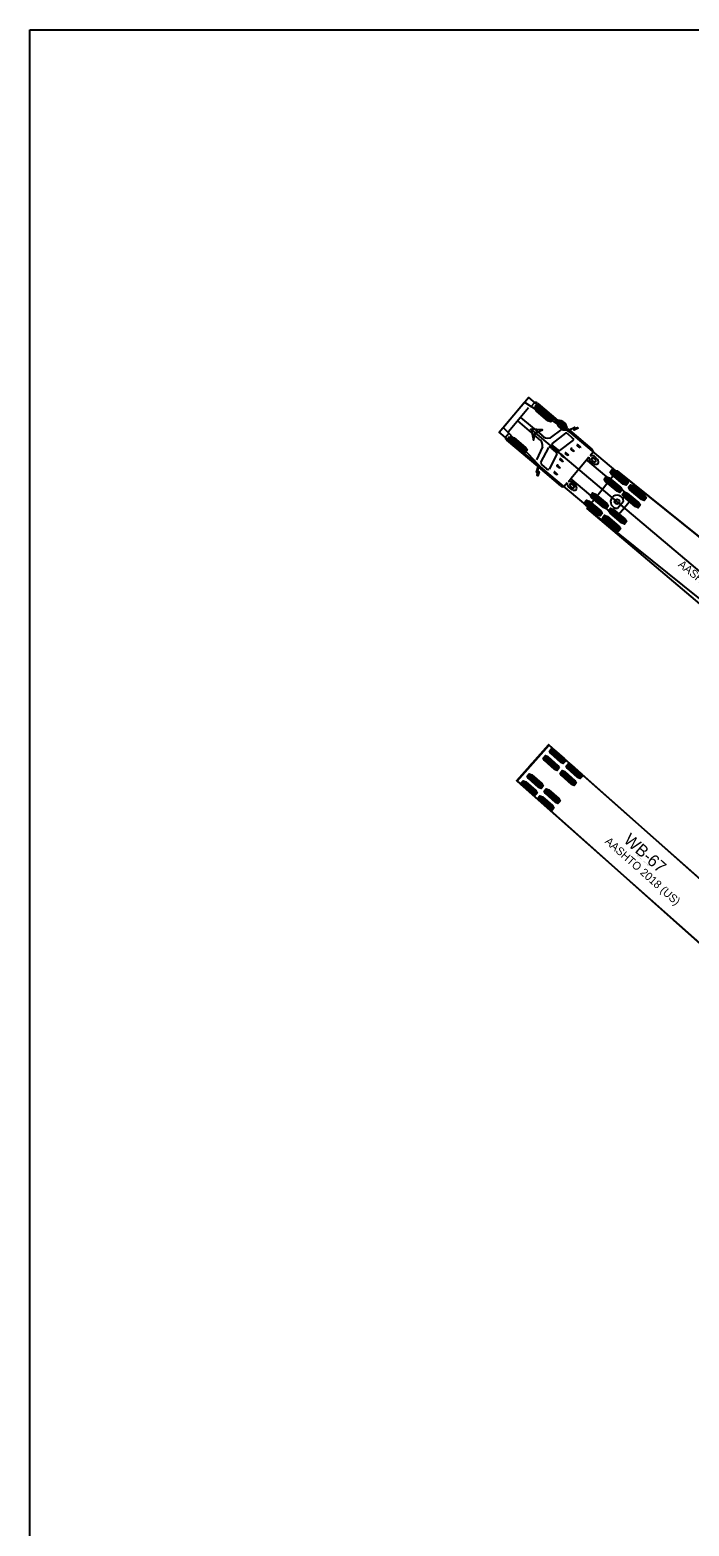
# Model space of a CAD drawing. Extents: x 973688 to 979179, y 703586 to 707602.
# Drawn here: x 976318.3 to 976435, y 705537.8 to 705802.7 of the extents above; entities that cross this region are included whole.
import ezdxf

# ---------------------------------------------------------------- set-up
doc = ezdxf.new("R2010")
doc.units = 0
for name, color, linetype in [('EB Right', 7, 'Continuous'), ('NO PLOT', 7, 'Continuous'), ('SB Right', 7, 'Continuous')]:
    doc.layers.add(name, color=color, linetype=linetype)

msp = doc.modelspace()

# ---------------------------------------------------------------- linework, layer by layer
at = {"layer": 'EB Right'}
for p, q in [((976404.6, 705669.7), (976410.24, 705676.06)), ((976413.09, 705673.23), (976410.62, 705675.42)), ((976407.01, 705672.53), (976407.19, 705672.73)), ((976407.37, 705672.93), (976407.42, 705672.88)), ((976407.54, 705673.13), (976407.72, 705673.33)), ((976411.69, 705671.65), (976409.22, 705673.84)), ((976411.84, 705671.82), (976409.37, 705674.01)), ((976411.99, 705671.99), (976409.52, 705674.19)), ((976412.78, 705672.89), (976410.31, 705675.08)), ((976412.93, 705673.06), (976410.47, 705675.25)), ((976416.08, 705670.57), (976413.61, 705672.76)), ((976408.84, 705668.45), (976406.38, 705670.64)), ((976409, 705668.62), (976406.53, 705670.81)), ((976409.15, 705668.79), (976406.68, 705670.98)), ((976414.68, 705669), (976412.21, 705671.19)), ((976414.83, 705669.17), (976412.36, 705671.36)), ((976414.98, 705669.34), (976412.51, 705671.53)), ((976415.77, 705670.23), (976413.31, 705672.42)), ((976415.93, 705670.4), (976413.46, 705672.59)), ((976407.75, 705667.21), (976405.28, 705669.4)), ((976407.9, 705667.39), (976405.43, 705669.58)), ((976408.05, 705667.56), (976405.58, 705669.75)), ((976411.84, 705665.79), (976409.37, 705667.98)), ((976411.99, 705665.96), (976409.52, 705668.16)), ((976412.14, 705666.14), (976409.67, 705668.33)), ((976410.74, 705664.56), (976408.27, 705666.75)), ((976410.89, 705664.73), (976408.42, 705666.92)), ((976411.04, 705664.9), (976408.58, 705667.09))]:
    msp.add_line(p, q, dxfattribs=at)
for points in [[(976442.37, 705636.04), (976434.45, 705643.15), (976418.56, 705657.31), (976404.49, 705669.8), (976410.14, 705676.15), (976410.14, 705676.15)], [(976404.56, 705669.77), (976404.55, 705669.75), (976404.6, 705669.7), (976408.84, 705665.94), (976444.14, 705634.62), (976446.96, 705637.8), (976449.78, 705640.98), (976414.48, 705672.3), (976410.24, 705676.06), (976410.19, 705676.11), (976410.17, 705676.09)], [(976410.16, 705676.07), (976410.16, 705676.07), (976407.74, 705673.35), (976407.72, 705673.33), (976407.67, 705673.37), (976407.67, 705673.37), (976407.49, 705673.17)], [(976410.14, 705676.15), (976440.9, 705648.86)], [(976407.14, 705672.78), (976406.96, 705672.58), (976406.96, 705672.58), (976407.01, 705672.53), (976406.99, 705672.5), (976404.58, 705669.79), (976404.58, 705669.79)], [(976407.54, 705673.12), (976407.19, 705672.73)]]:
    msp.add_lwpolyline(points, dxfattribs=at)
for points in [[(976413.12, 705673.27), (976412.74, 705672.84), (976412.28, 705673.02), (976410.51, 705674.6), (976410.28, 705675.03), (976410.66, 705675.46), (976411.12, 705675.28), (976412.89, 705673.71)], [(976412.03, 705672.04), (976411.65, 705671.61), (976411.19, 705671.79), (976409.41, 705673.36), (976409.18, 705673.8), (976409.56, 705674.23), (976410.02, 705674.05), (976411.8, 705672.47)], [(976416.12, 705670.62), (976415.74, 705670.19), (976415.28, 705670.37), (976413.5, 705671.94), (976413.27, 705672.38), (976413.65, 705672.81), (976414.11, 705672.63), (976415.88, 705671.05)], [(976409.19, 705668.83), (976408.81, 705668.41), (976408.35, 705668.58), (976406.57, 705670.16), (976406.34, 705670.6), (976406.72, 705671.02), (976407.18, 705670.85), (976408.95, 705669.27)], [(976415.02, 705669.38), (976414.64, 705668.95), (976414.18, 705669.13), (976412.4, 705670.71), (976412.17, 705671.14), (976412.55, 705671.57), (976413.01, 705671.4), (976414.79, 705669.82)], [(976408.09, 705667.6), (976407.71, 705667.17), (976407.25, 705667.35), (976405.47, 705668.93), (976405.24, 705669.36), (976405.62, 705669.79), (976406.08, 705669.61), (976407.86, 705668.03)], [(976412.18, 705666.18), (976411.8, 705665.75), (976411.34, 705665.93), (976409.56, 705667.51), (976409.33, 705667.94), (976409.71, 705668.37), (976410.17, 705668.19), (976411.95, 705666.61)], [(976411.08, 705664.94), (976410.7, 705664.52), (976410.24, 705664.69), (976408.47, 705666.27), (976408.23, 705666.71), (976408.61, 705667.13), (976409.07, 705666.96), (976410.85, 705665.38)]]:
    msp.add_lwpolyline(points, close=True, dxfattribs=at)
for centre in [(976410.14, 705676.11), (976404.54, 705669.8)]:
    msp.add_circle(centre, 0.0266, dxfattribs=at)
for centre, radius, start, end in [((976410.14, 705676.11), 0.0363, 337.4928, 298.6541), ((976407.17, 705672.76), 0.0354, 142.7069, 314.8923), ((976407.17, 705672.76), 0.0352, 319.3896, 138.3901), ((976407.51, 705673.15), 0.0352, 138.4406, 317.441), ((976407.51, 705673.15), 0.0353, 321.7515, 140.1012), ((976403.05, 705671.11), 2.02, 318.4153, 319.0991)]:
    msp.add_arc(centre, radius, start, end, dxfattribs=at)
at = {"layer": 'NO PLOT'}
msp.add_lwpolyline([(976318.34, 705802.71), (976998.34, 705802.71), (976998.34, 705362.71), (976318.34, 705362.71)], close=True, dxfattribs=at)
at = {"layer": 'SB Right'}
for p, q in [((976407.91, 705736.29), (976407.65, 705735.97)), ((976408.18, 705736.06), (976407.91, 705736.29)), ((976406.6, 705735.82), (976403.01, 705731.57)), ((976405.17, 705734.12), (976408.91, 705730.97)), ((976411.58, 705733.02), (976407.06, 705736.02)), ((976407.65, 705735.97), (976407.92, 705735.74)), ((976407.77, 705735.71), (976410.57, 705733.35)), ((976407.92, 705735.74), (976408.18, 705736.06)), ((976407.92, 705735.89), (976410.72, 705733.52)), ((976408.07, 705736.06), (976410.87, 705733.7)), ((976410.08, 705723.88), (976403.08, 705731.3)), ((976404.63, 705733.48), (976408.37, 705730.33)), ((976549.41, 705611.94), (976407.04, 705732)), ((976410.46, 705730.51), (976412.54, 705732)), ((976413.13, 705731.3), (976410.74, 705729.47)), ((976415.56, 705730.37), (976413.22, 705731.93)), ((976414.38, 705730.46), (976413.52, 705731.19)), ((976413.84, 705731.82), (976413.76, 705731.89)), ((976414.82, 705732.18), (976414.84, 705732.2)), ((976414.84, 705732.2), (976414.87, 705732.21)), ((976402.96, 705730.41), (976403.23, 705730.73)), ((976403.23, 705730.18), (976402.96, 705730.41)), ((976403.2, 705730.3), (976406.01, 705727.93)), ((976403.23, 705730.73), (976403.5, 705730.5)), ((976403.5, 705730.5), (976403.23, 705730.18)), ((976403.35, 705730.47), (976406.15, 705728.11)), ((976403.5, 705730.65), (976406.3, 705728.28)), ((976409.08, 705728.88), (976407.97, 705726.58)), ((976408.75, 705726.11), (976410.15, 705728.77)), ((976410.57, 705728.68), (976411.43, 705727.96)), ((976410.9, 705729.08), (976411.76, 705728.35)), ((976412.15, 705728.24), (976414.54, 705730.07)), ((976414.62, 705728.06), (976414.18, 705728.38)), ((976414.29, 705728.51), (976414.68, 705728.13)), ((976415.7, 705728.74), (976415.26, 705729.07)), ((976415.37, 705729.19), (976415.76, 705728.81)), ((976415.76, 705728.81), (976415.7, 705728.74)), ((976409.8, 705725.02), (976408.93, 705725.75)), ((976411.61, 705727.59), (976410.21, 705724.93)), ((976412.67, 705726.26), (976412.23, 705726.59)), ((976412.34, 705726.72), (976412.73, 705726.33)), ((976412.89, 705727), (976412.45, 705727.33)), ((976412.56, 705727.46), (976412.95, 705727.07)), ((976412.73, 705726.33), (976412.67, 705726.26)), ((976412.95, 705727.07), (976412.89, 705727)), ((976413.58, 705727.34), (976413.14, 705727.67)), ((976413.25, 705727.8), (976413.64, 705727.41)), ((976413.64, 705727.41), (976413.58, 705727.34)), ((976416.84, 705726.56), (976414.05, 705723.25)), ((976414.68, 705728.13), (976414.62, 705728.06)), ((976408.17, 705724.29), (976408.15, 705724.27)), ((976408.15, 705724.27), (976408.15, 705724.25)), ((976408.36, 705725.33), (976408.28, 705725.39)), ((976411.65, 705723.94), (976411.21, 705724.26)), ((976411.32, 705724.39), (976411.71, 705724.01)), ((976411.71, 705724.01), (976411.65, 705723.94)), ((976412.14, 705725.12), (976411.68, 705725.46)), ((976411.79, 705725.59), (976412.2, 705725.19)), ((976412.2, 705725.19), (976412.14, 705725.12)), ((976420.01, 705723.24), (976422.81, 705720.87)), ((976420.16, 705723.41), (976422.96, 705721.05)), ((976420.3, 705723.59), (976423.11, 705721.22)), ((976421.07, 705724.5), (976423.88, 705722.13)), ((976421.22, 705724.67), (976424.02, 705722.31)), ((976421.37, 705724.85), (976424.17, 705722.48)), ((976417.57, 705720.34), (976420.37, 705717.98)), ((976417.72, 705720.52), (976420.52, 705718.15)), ((976417.87, 705720.69), (976420.67, 705718.33)), ((976423.22, 705720.53), (976426.02, 705718.16)), ((976423.37, 705720.7), (976426.17, 705718.34)), ((976423.51, 705720.88), (976426.32, 705718.51)), ((976424.28, 705721.79), (976427.09, 705719.43)), ((976424.43, 705721.96), (976427.23, 705719.6)), ((976424.58, 705722.14), (976427.38, 705719.78)), ((976416.51, 705719.08), (976419.31, 705716.72)), ((976416.65, 705719.26), (976419.46, 705716.89)), ((976416.8, 705719.43), (976419.6, 705717.07)), ((976420.93, 705717.81), (976423.73, 705715.45)), ((976421.08, 705717.99), (976423.88, 705715.62)), ((976422.34, 705718.04), (976423.38, 705719.28)), ((976419.72, 705716.37), (976422.52, 705714.01)), ((976419.86, 705716.55), (976422.67, 705714.19)), ((976420.01, 705716.72), (976422.82, 705714.36)), ((976420.78, 705717.64), (976423.58, 705715.27))]:
    msp.add_line(p, q, dxfattribs=at)
for points in [[(976445.35, 705693.94), (976416.94, 705718), (976417.11, 705718.27), (976401.4, 705731.52), (976406.56, 705737.64), (976421.98, 705724.63), (976422.27, 705724.62), (976463.24, 705691.7)], [(976402.52, 705730.63), (976403.07, 705731.29), (976403.08, 705731.3), (976402.09, 705732.34), (976402.13, 705732.39), (976403.98, 705734.58), (976405.82, 705736.77), (976405.87, 705736.81), (976407.06, 705736.02), (976407.07, 705736.03), (976407.62, 705736.68)], [(976408.21, 705736.57), (976411.76, 705733.58)], [(976407.04, 705732), (976407.46, 705730.05), (976407.8, 705731.35), (976409.03, 705731.91), (976407.04, 705732)], [(976413.43, 705732.17), (976413.75, 705731.89), (976413.77, 705731.89), (976414.67, 705732.32)], [(976414.8, 705732.27), (976414.87, 705732.21), (976414.87, 705732.21), (976415.26, 705732.3), (976415.26, 705732.3), (976415.35, 705732.22), (976415.35, 705732.22), (976414.69, 705731.84), (976414.61, 705731.9), (976414.82, 705732.18), (976414.82, 705732.18), (976414.76, 705732.23), (976414.76, 705732.23), (976414.76, 705732.23), (976414.72, 705732.25), (976414.72, 705732.25), (976413.84, 705731.82), (976417.79, 705728.49)], [(976408.01, 705724.42), (976408.28, 705725.38), (976408.27, 705725.4), (976402.73, 705730.07)], [(976417.28, 705727.09), (976416.84, 705726.56), (976417.02, 705726.41), (976424.94, 705719.73), (976423.55, 705718.07), (976422.15, 705716.42), (976414.23, 705723.1), (976414.05, 705723.25), (976413.61, 705722.73)], [(976418.01, 705727.95), (976417.47, 705727.3)], [(976412.31, 705721.99), (976408.36, 705725.33), (976408.09, 705724.38), (976408.09, 705724.38), (976408.11, 705724.35), (976408.11, 705724.35), (976408.11, 705724.35), (976408.17, 705724.29), (976408.17, 705724.29), (976408.41, 705724.55), (976408.49, 705724.48), (976408.22, 705723.77), (976408.22, 705723.77), (976408.13, 705723.84), (976408.13, 705723.85), (976408.15, 705724.24), (976408.15, 705724.25), (976408.08, 705724.3)], [(976463.51, 705691.44), (976463.52, 705691.46), (976463.47, 705691.5), (976459.05, 705695.06), (976422.27, 705724.62), (976419.61, 705721.31), (976416.94, 705718), (976453.73, 705688.43), (976458.14, 705684.88), (976458.2, 705684.84), (976458.21, 705684.85)], [(976413.43, 705722.51), (976412.88, 705721.87)]]:
    msp.add_lwpolyline(points, dxfattribs=at)
for points in [[(976407.73, 705735.67), (976408.1, 705736.11), (976408.61, 705735.91), (976410.62, 705734.21), (976410.91, 705733.74), (976410.54, 705733.31), (976410.03, 705733.51), (976408.01, 705735.21)], [(976407.04, 705732), (976407.46, 705730.05), (976407.8, 705731.35), (976409.03, 705731.91)], [(976403.17, 705730.25), (976403.54, 705730.69), (976404.04, 705730.49), (976406.06, 705728.79), (976406.34, 705728.33), (976405.97, 705727.89), (976405.47, 705728.09), (976403.45, 705729.79)], [(976419.97, 705723.19), (976420.34, 705723.63), (976420.84, 705723.43), (976422.86, 705721.73), (976423.14, 705721.27), (976422.77, 705720.83), (976422.27, 705721.03), (976420.25, 705722.73)], [(976421.04, 705724.45), (976421.4, 705724.89), (976421.91, 705724.69), (976423.93, 705722.99), (976424.21, 705722.53), (976423.84, 705722.09), (976423.34, 705722.29), (976421.32, 705723.99)], [(976417.53, 705720.3), (976417.9, 705720.74), (976418.41, 705720.54), (976420.42, 705718.84), (976420.7, 705718.37), (976420.34, 705717.94), (976419.83, 705718.13), (976417.81, 705719.84)], [(976423.18, 705720.48), (976423.55, 705720.92), (976424.05, 705720.72), (976426.07, 705719.02), (976426.35, 705718.56), (976425.99, 705718.12), (976425.48, 705718.32), (976423.46, 705720.02)], [(976424.25, 705721.75), (976424.62, 705722.18), (976425.12, 705721.98), (976427.14, 705720.28), (976427.42, 705719.82), (976427.05, 705719.38), (976426.55, 705719.58), (976424.53, 705721.28)], [(976416.47, 705719.04), (976416.84, 705719.48), (976417.34, 705719.28), (976419.36, 705717.57), (976419.64, 705717.11), (976419.27, 705716.67), (976418.77, 705716.87), (976416.75, 705718.58)], [(976420.74, 705717.59), (976421.11, 705718.03), (976421.62, 705717.83), (976423.63, 705716.13), (976423.92, 705715.67), (976423.55, 705715.23), (976423.04, 705715.43), (976421.03, 705717.13)], [(976419.68, 705716.33), (976420.05, 705716.77), (976420.55, 705716.57), (976422.57, 705714.87), (976422.85, 705714.4), (976422.48, 705713.97), (976421.98, 705714.17), (976419.96, 705715.87)]]:
    msp.add_lwpolyline(points, close=True, dxfattribs=at)
for centre, radius in [((976407.04, 705732), 0.0417), ((976422.25, 705719.19), 0.424)]:
    msp.add_circle(centre, radius, dxfattribs=at)
for centre, radius, start, end in [((976407.84, 705736.25), 0.486, 41.4472, 117.3983), ((976411.9, 705732.05), 1.53, 4.354, 95.3631), ((976410.04, 705731.97), 1.52, 221.4413, 285.8688), ((976411.97, 705733.19), 0.425, 117.9242, 204.4606), ((976413.18, 705733.59), 1.7, 199.782, 235.69), ((976412.28, 705733), 0.366, 147.9136, 220.3946), ((976412.25, 705732.62), 0.634, 40.4452, 116.4469), ((976413.02, 705733.37), 1.19, 210.9925, 246.8818), ((976412.35, 705732.89), 0.158, 144.8325, 206.3453), ((976412.74, 705733.04), 0.575, 202.9364, 239.5067), ((976412.36, 705732.8), 0.223, 57.0962, 126.6987), ((976412.98, 705733.04), 1.14, 228.5658, 282.3684), ((976412.62, 705732.74), 0.263, 228.7962, 302.6981), ((976412.24, 705732.45), 0.589, 22.6168, 65.5995), ((976412.76, 705732.67), 0.44, 241.6555, 305.4684), ((976412.09, 705732.23), 1.03, 22.6849, 51.0715), ((976412.62, 705732.61), 0.17, 327.5304, 21.5947), ((976412.76, 705732.48), 0.317, 325.7115, 27.3039), ((976413.23, 705730.93), 0.387, 42.2965, 105.5284), ((976413.09, 705732.25), 0.347, 292.1885, 346.9991), ((976414.72, 705732.3), 0.0522, 48.7439, 153.5985), ((976414.69, 705732.24), 0.108, 12.8376, 59.0201), ((976402.98, 705730.49), 0.486, 162.3243, 238.2754), ((976407.57, 705729.04), 1.52, 353.8538, 58.2813), ((976410.32, 705728.52), 0.296, 32.8449, 123.1425), ((976411.02, 705729.35), 0.296, 156.5801, 246.8777), ((976412.05, 705728.61), 0.387, 222.2989, 285.526), ((976414.15, 705728.44), 0.157, 29.2057, 116.3153), ((976414.26, 705728.55), 0.184, 171.0161, 242.9081), ((976414.22, 705730.17), 0.332, 342.5179, 60.9399), ((976415.23, 705729.12), 0.157, 29.2057, 116.3153), ((976415.34, 705729.23), 0.184, 171.0161, 242.9081), ((976417.39, 705728.01), 0.619, 354.0216, 49.8633), ((976409.14, 705726.07), 0.387, 174.1941, 237.4261), ((976411.22, 705727.63), 0.387, 354.1966, 57.4237), ((976411.75, 705725.59), 0.157, 163.4073, 250.5169), ((976411.66, 705725.46), 0.184, 36.8145, 108.7065), ((976412.28, 705726.74), 0.157, 163.4073, 250.5169), ((976412.19, 705726.61), 0.184, 36.8145, 108.7065), ((976412.5, 705727.47), 0.157, 163.4073, 250.5169), ((976412.42, 705727.38), 0.157, 29.2057, 116.3153), ((976413.11, 705727.72), 0.157, 29.2057, 116.3153), ((976413.22, 705727.83), 0.184, 171.0161, 242.9081), ((976418, 705726.98), 0.729, 171.5388, 214.0528), ((976418.88, 705727.47), 1.73, 211.2361, 236.0347), ((976417.67, 705726.19), 1.14, 45.4401, 100.2314), ((976417.89, 705726.76), 0.169, 101.3083, 201.427), ((976418.43, 705726.93), 0.732, 198.453, 244.6875), ((976417.9, 705726.4), 0.522, 47.6918, 94.8559), ((976418.6, 705726.94), 1.14, 232.5766, 274.0973), ((976418.31, 705726.57), 0.362, 236.5238, 285.5647), ((976417.87, 705726.24), 0.664, 16.7358, 54.9575), ((976418.35, 705726.38), 0.172, 292.4091, 19.5597), ((976417.59, 705725.88), 1.42, 14.8653, 51.9331), ((976418.63, 705726.15), 0.346, 279.4555, 16.4686), ((976408.04, 705724.38), 0.0522, 126.1241, 230.9787), ((976408.09, 705724.41), 0.108, 220.7025, 266.885), ((976410.05, 705725.23), 0.332, 218.7827, 297.2047), ((976411.26, 705724.41), 0.157, 163.4073, 250.5169), ((976411.17, 705724.28), 0.184, 36.8145, 108.7065), ((976412.71, 705722.46), 0.619, 229.8593, 285.701), ((976414.56, 705722.5), 1.14, 179.4912, 234.2825), ((976413.83, 705722.04), 0.729, 65.6698, 108.1838), ((976414.04, 705722.19), 0.169, 78.2956, 178.4143), ((976414.39, 705722.24), 0.522, 184.8667, 232.0308), ((976414.85, 705722.63), 1.42, 227.7894, 264.8573), ((976413.96, 705721.63), 0.732, 35.0351, 81.2696), ((976414.54, 705722.29), 0.664, 224.7651, 262.9868), ((976413.5, 705721.09), 1.73, 43.6879, 68.4864), ((976414.49, 705721.8), 0.172, 260.1629, 347.3135), ((976414.29, 705721.8), 0.362, 354.1579, 43.1988), ((976414.76, 705721.56), 0.346, 263.254, 0.267), ((976413.98, 705721.45), 1.14, 5.6253, 47.146), ((976422.25, 705719.18), 1.14, 4.8613, 274.8613)]:
    msp.add_arc(centre, radius, start, end, dxfattribs=at)
for centre, major_axis, start_param, end_param in [((976414.73, 705732.29), (-0.0598, 0.0504), 0.569648, 1.840391), ((976414.73, 705732.29), (-0.0598, 0.0504), 2.398717, 3.668019), ((976408.05, 705724.36), (0.0598, -0.0504), 1.301202, 2.571945), ((976408.05, 705724.36), (-0.0598, 0.0504), 2.615166, 3.884468)]:
    msp.add_ellipse(centre, major_axis=major_axis, ratio=0.544872, start_param=start_param, end_param=end_param, dxfattribs=at)

# ---------------------------------------------------------------- texts
at = {"layer": 'EB Right'}
for s, height, p in [('AASHTO 2018 (US)', 1.4167, (976419.99, 705658.88)), ('WB-67', 2.125, (976423.27, 705659.04)), ('(c) 2020 Transoft Solutions, Inc. All rights reserved.', 0.085, (976425.8, 705656.51))]:
    msp.add_text(s, height=height, rotation=318.4153, dxfattribs=at).set_placement(p)
at = {"layer": 'SB Right'}
msp.add_text('AASHTO 2018 (US)', height=1.4167, rotation=321.2084, dxfattribs=at).set_placement((976432.95, 705707.85))

doc.saveas('drawing.dxf')
